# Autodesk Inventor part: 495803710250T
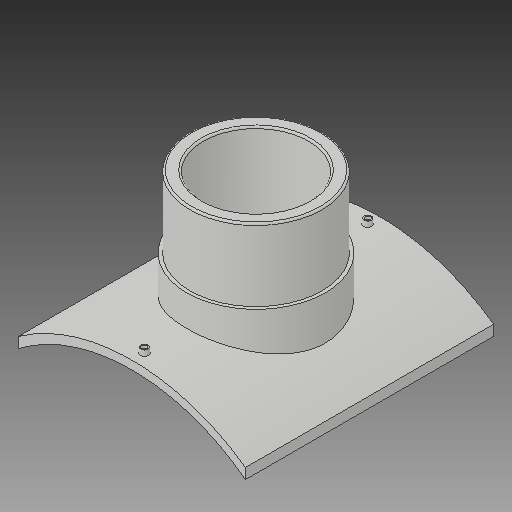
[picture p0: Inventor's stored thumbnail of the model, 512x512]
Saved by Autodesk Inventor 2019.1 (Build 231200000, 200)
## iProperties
Created: 2017-10
Part Number: 495803710250T
Material: Generic
Description: PLASSON BRANCH SADDLE  710x250
Document SubType Name: Modeling
Designer: KIM
Mass: 2754.05 g
Surface Area: 3037.44 cm^2
Volume: 2754.05 cm^3
Density: 1 g/cm^3
Appearance: Default
Author: KIM
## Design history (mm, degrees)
derived "495803.ipt"
feature "Solid1::495803.ipt"
tag "TaggingFeature1"
body "Solid1"
other parameters: "d1" = 16, "d4" = 0, "d12" = 380.6, "d13" = 14, "d14" = 211.5, "d16" = 5 deg, "d18" = 4, "d19" = 14, "d20" = 0, "d21" = 3, "d22" = 0, "d23" = 566, "d24" = 262.5, "d25" = 16, "d28" = 0, "d29" = 9.6, "d31" = 0, "d32" = 97.5, "d33" = 0, "d34" = 7.1, "d37" = 136.5, "d38" = 0, "d39" = 3.55, "H_" = 195, "x_" = 16, "D_" = 16
